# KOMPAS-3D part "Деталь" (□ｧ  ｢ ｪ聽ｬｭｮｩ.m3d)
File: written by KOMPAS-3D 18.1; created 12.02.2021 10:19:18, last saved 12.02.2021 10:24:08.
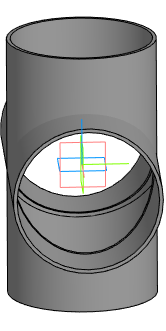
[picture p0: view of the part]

Document properties: Полное имя файла: C:\GoogleDrive\НИР\ИКИ\Компас\База вакуумной.m3d

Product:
- Part/product: Деталь
    Масса: 6.02592
  - Body: Тело 2
      Масса: 3.01682
  - Body: Тело 1
      Масса: 3.0091

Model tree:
1. Эскиз:1
2. Элемент выдавливания:1
     Расстояние 1 = 140; Расстояние 2 = 140
3. Эскиз:2
4. Элемент выдавливания:2
     Расстояние 1 = 140; Расстояние 2 = 140
5. Эскиз:3  (with: Элемент выдавливания:2)
6. Элемент выдавливания:3
     Расстояние 2 = 280
7. Эскиз:4  (with: Элемент выдавливания:1)
8. Элемент выдавливания:4
     Расстояние 2 = 280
